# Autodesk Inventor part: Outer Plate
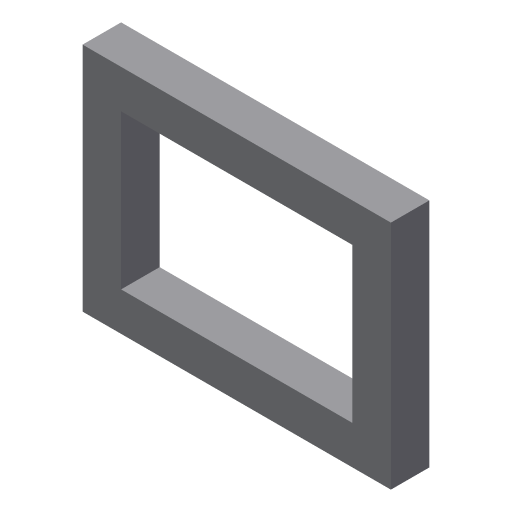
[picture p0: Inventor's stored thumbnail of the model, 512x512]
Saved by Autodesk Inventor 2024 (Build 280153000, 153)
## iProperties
Created: 2010-04
Part Number: Outer Plate
Document SubType Name: Modeling
Designer: CADSoft
Density: 1 g/cm^3
Material: Generic
Appearance: Default
Author: CADSoft
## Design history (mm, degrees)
sketch "Sketch1"
  geometry: L1 (-40, 30)-(40, 30); L2 (40, 30)-(40, -30); L3 (40, -30)-(-40, -30); L4 (-40, -30)-(-40, 30); L5 (-30, 20)-(30, 20); L6 (30, 20)-(30, -20); L7 (30, -20)-(-30, -20); L8 (-30, -20)-(-30, 20); 1 further point
  constraints: 16 end point, 4 parallel, 2 horizontal, 2 perpendicular
  dimensions: "d0" = 80 distance of L1.start L1.end; "d1" = 60 distance of L5.start L5.end; "d2" = 10 distance between parallel lines of L4 L8; "d3" = 10 distance between parallel lines of L1 L5; "d4" = 40 distance of L7.end L5.start; "d5" = 60 distance of L3.end L1.start
extrude "Extrusion1" new body sketch "Sketch1" distance "d8" = 10; taper "d9" = 0 deg
body "Solid1"
